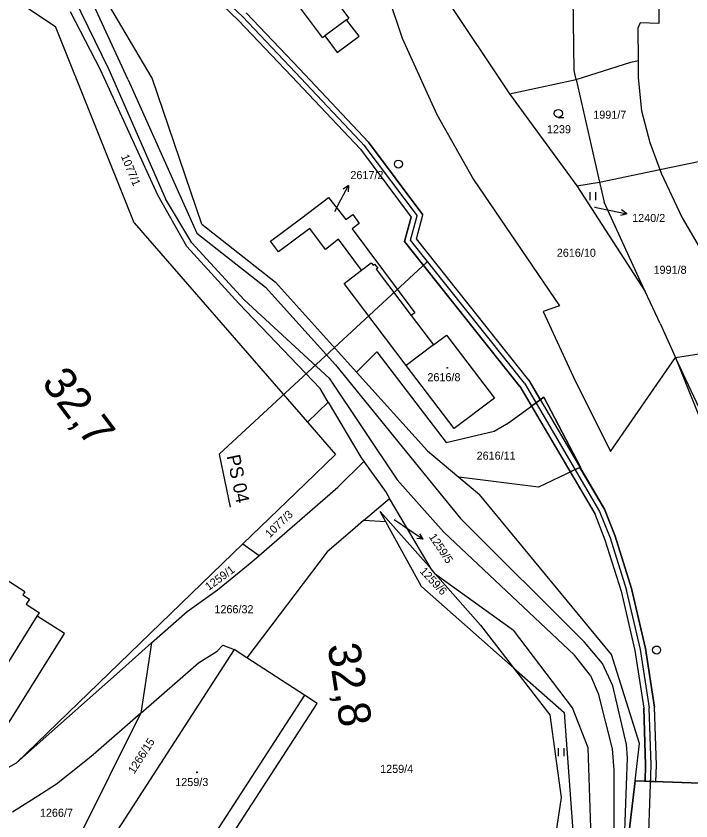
# Model space of a CAD drawing. Extents: x -804166 to -803706, y -1151030 to -1150147.
# Drawn here: x -803978.8 to -803853.6, y -1150580.2 to -1150430.9 of the extents above; entities that cross this region are included whole.
import ezdxf

# ---------------------------------------------------------------- set-up
doc = ezdxf.new("R2010")
doc.units = 0
for name, color, linetype in [('Default', 7, 'Continuous'), ('kilometráž - vrstava 7', 7, 'Continuous'), ('kn_celek - Cisla parcel pomocna', 7, 'Continuous'), ('kn_celek - Cisla pozemkovych parcel', 7, 'Continuous'), ('kn_celek - Cisla stavebnich parcel', 7, 'Continuous'), ('kn_celek - Hranice parcel', 7, 'Continuous'), ('kn_celek - Vnitrni kresby', 7, 'Continuous'), ('kn_celek - Znacky budov', 7, 'Continuous'), ('kn_celek - Znacky kultur', 7, 'Continuous'), ('plochy - CD', 7, 'Continuous'), ('plochy - DZ_ostat', 7, 'Continuous'), ('plochy - SZDC', 7, 'Continuous'), ('plochy - VB', 7, 'Continuous'), ('PSR_C2_2_trasa_Vimperk - Kabelová trasa', 7, 'Continuous'), ('SOPS', 7, 'Continuous')]:
    doc.layers.add(name, color=color, linetype=linetype)

# ---------------------------------------------------------------- blocks, each defined once
blk = doc.blocks.new('304')
at = {"layer": 'Default'}
blk.add_line((-0.1, 0), (9.9, 0), dxfattribs=at)
blk.add_circle((-0.1, 7.5), 7.5, dxfattribs=at)
blk = doc.blocks.new('306')
at = {"layer": 'Default'}
for p, q in [((-5.2, 0), (-5.2, 15)), ((4.8, 0), (4.8, 15))]:
    blk.add_line(p, q, dxfattribs=at)
blk = doc.blocks.new('402')
at = {"layer": 'Default'}
for p, q in [((-0.8, 0.8), (0.7, 0.8)), ((-0.8, 0.8), (-0.8, -0.7)), ((0.7, 0.8), (0.7, -0.7)), ((0.7, -0.7), (-0.8, -0.7))]:
    blk.add_line(p, q, dxfattribs=at)
blk = doc.blocks.new('Z61')
at = {"layer": 'Default'}
for p, q in [((0, 0), (30, 0)), ((30, 0), (19.2, 5.3)), ((30, 0), (19.2, -5.3))]:
    blk.add_line(p, q, dxfattribs=at)

msp = doc.modelspace()

# ---------------------------------------------------------------- linework, layer by layer
at = {"layer": 'kilometráž - vrstava 7'}
for centre in [(-803907.87, -1150458.35), (-803859.96, -1150548.47)]:
    msp.add_circle(centre, 0.75, dxfattribs=at)
at = {"layer": 'kn_celek - Cisla parcel pomocna'}
for p, q in [((-803919.68, -1150467.14), (-803918.53, -1150464.96)), ((-803871.51, -1150466.36), (-803868.44, -1150466.99)), ((-803908.68, -1150524.26), (-803905.75, -1150526.25))]:
    msp.add_line(p, q, dxfattribs=at)
at = {"layer": 'kn_celek - Hranice parcel'}
for p, q in [((-804026.79, -1150395.95), (-803971.47, -1150432.84)), ((-803859.7, -1150404.14), (-803859.55, -1150432.31)), ((-803875.26, -1150441.02), (-803875.68, -1150406.78)), ((-803932.96, -1150410.23), (-803917.09, -1150431.3)), ((-803921.93, -1150434.85), (-803937.77, -1150413.78)), ((-803903.99, -1150420.19), (-803887.28, -1150445.33)), ((-803953.58, -1150442.45), (-803965.92, -1150421.41)), ((-803909.89, -1150426.9), (-803907.15, -1150435.03)), ((-803963.14, -1150440.87), (-803968.72, -1150430.14)), ((-803917.49, -1150431.6), (-803917.09, -1150431.3)), ((-803915.17, -1150434.66), (-803917.49, -1150431.6)), ((-803863.03, -1150432.19), (-803863.45, -1150433.16)), ((-803859.55, -1150432.31), (-803863.03, -1150432.19)), ((-803956.89, -1150469.24), (-803971.47, -1150432.84)), ((-803863.45, -1150433.16), (-803863.4, -1150439.15)), ((-803921.93, -1150434.85), (-803921.53, -1150434.55)), ((-803921.53, -1150434.55), (-803919.22, -1150437.65)), ((-803919.22, -1150437.65), (-803915.17, -1150434.66)), ((-803907.15, -1150435.03), (-803900.76, -1150449.16)), ((-803874.89, -1150442.65), (-803864.75, -1150439.43)), ((-803864.75, -1150439.43), (-803863.4, -1150439.15)), ((-803863.4, -1150439.15), (-803863.37, -1150442.39)), ((-803952.5, -1150464.09), (-803963.14, -1150440.87)), ((-803874.89, -1150442.65), (-803875.26, -1150441.02)), ((-803944.36, -1150469.51), (-803953.58, -1150442.45)), ((-803887.28, -1150445.33), (-803874.89, -1150442.65)), ((-803874.89, -1150442.65), (-803870.54, -1150461.68)), ((-803863.37, -1150442.39), (-803862.79, -1150448.49)), ((-803887.28, -1150445.33), (-803874.77, -1150462.41)), ((-803862.79, -1150448.49), (-803861.22, -1150454.33)), ((-803900.76, -1150449.16), (-803893.94, -1150461.19)), ((-803861.22, -1150454.33), (-803859.37, -1150459.36)), ((-803859.37, -1150459.36), (-803848.47, -1150457.09)), ((-803870.54, -1150461.68), (-803859.37, -1150459.36)), ((-803859.37, -1150459.36), (-803859.13, -1150460.01)), ((-803859.13, -1150460.01), (-803855.19, -1150468.33)), ((-803893.94, -1150461.19), (-803877.95, -1150484.62)), ((-803874.77, -1150462.41), (-803870.54, -1150461.68)), ((-803870.54, -1150461.68), (-803869.68, -1150465.41)), ((-803874.77, -1150462.41), (-803862.07, -1150481.98)), ((-803947.12, -1150473.61), (-803952.5, -1150464.09)), ((-803925.79, -1150468.33), (-803920.83, -1150464.56)), ((-803920.83, -1150464.56), (-803917.63, -1150468.64)), ((-803863.6, -1150478.64), (-803869.68, -1150465.41)), ((-803917.63, -1150468.64), (-803916.3, -1150467.69)), ((-803916.3, -1150467.69), (-803915.12, -1150469.35)), ((-803956.89, -1150469.24), (-803924.74, -1150506.24)), ((-803944.36, -1150469.51), (-803930.65, -1150480.27)), ((-803931.57, -1150472.66), (-803925.79, -1150468.33)), ((-803915.12, -1150469.35), (-803916.46, -1150470.34)), ((-803855.19, -1150468.33), (-803852.25, -1150473.4)), ((-803924.33, -1150470.27), (-803930.11, -1150474.6)), ((-803921.41, -1150474.2), (-803924.33, -1150470.27)), ((-803916.46, -1150470.34), (-803904.84, -1150485.91)), ((-803930.11, -1150474.6), (-803931.57, -1150472.66)), ((-803919.01, -1150472.26), (-803921.41, -1150474.2)), ((-803914.71, -1150478.01), (-803919.01, -1150472.26)), ((-803947.12, -1150473.61), (-803937.45, -1150484.2)), ((-803914.71, -1150478.01), (-803912.92, -1150476.64)), ((-803912.92, -1150476.64), (-803912.56, -1150477.11)), ((-803912.56, -1150477.11), (-803912.3, -1150476.91)), ((-803912.3, -1150476.91), (-803911.71, -1150477.67)), ((-803917.95, -1150480.48), (-803914.71, -1150478.01)), ((-803911.71, -1150477.67), (-803911.98, -1150477.87)), ((-803911.98, -1150477.87), (-803905.5, -1150486.41)), ((-803862.07, -1150481.98), (-803863.6, -1150478.64)), ((-803915.62, -1150496.95), (-803930.65, -1150480.27)), ((-803906.42, -1150495.69), (-803917.95, -1150480.48)), ((-803859.3, -1150487.93), (-803862.07, -1150481.98)), ((-803937.45, -1150484.2), (-803922.41, -1150499.99)), ((-803877.95, -1150484.62), (-803881.02, -1150485.69)), ((-803904.84, -1150485.91), (-803905.5, -1150486.41)), ((-803881.02, -1150485.69), (-803875.42, -1150497.74)), ((-803905.5, -1150486.41), (-803901.34, -1150491.89)), ((-803859.3, -1150487.93), (-803856.47, -1150494.21)), ((-803901.34, -1150491.89), (-803898.96, -1150490.08)), ((-803898.96, -1150490.08), (-803890.06, -1150501.75)), ((-803856.47, -1150494.21), (-803836.01, -1150490.97)), ((-803915.62, -1150496.95), (-803911.88, -1150493.16)), ((-803911.88, -1150493.16), (-803899.02, -1150510.01)), ((-803868.53, -1150511.63), (-803856.47, -1150494.21)), ((-803851.14, -1150505.55), (-803856.47, -1150494.21)), ((-803856.47, -1150494.21), (-803850.2, -1150509.77)), ((-803897.53, -1150507.41), (-803906.42, -1150495.69)), ((-803902.47, -1150511.55), (-803915.62, -1150496.95)), ((-803875.42, -1150497.74), (-803868.53, -1150511.63)), ((-803920.92, -1150502.5), (-803922.41, -1150499.99)), ((-803924.74, -1150506.24), (-803920.92, -1150502.5)), ((-803920.92, -1150502.5), (-803914.87, -1150512.69)), ((-803890.06, -1150501.75), (-803897.53, -1150507.41)), ((-803887.46, -1150506.35), (-803880.9, -1150501.6)), ((-803880.9, -1150501.6), (-803874.06, -1150514.53)), ((-803924.74, -1150506.24), (-803919.56, -1150512.21)), ((-803890.08, -1150507.89), (-803887.46, -1150506.35)), ((-803899.02, -1150510.01), (-803890.08, -1150507.89)), ((-803919.56, -1150512.21), (-803925.19, -1150517.65)), ((-803914.87, -1150512.69), (-803914.28, -1150513.51)), ((-803902.47, -1150511.55), (-803896.64, -1150516.44)), ((-803919.12, -1150518.27), (-803914.28, -1150513.51)), ((-803914.28, -1150513.51), (-803910.12, -1150519.28)), ((-803874.06, -1150514.53), (-803881.88, -1150518.24)), ((-803881.88, -1150518.24), (-803896.64, -1150516.44)), ((-803896.64, -1150516.44), (-803892.84, -1150519.63)), ((-803925.19, -1150517.65), (-803936.74, -1150528.8)), ((-803933.72, -1150530.91), (-803919.12, -1150518.27)), ((-803914.32, -1150524.45), (-803909.5, -1150520.37)), ((-803910.12, -1150519.28), (-803909.5, -1150520.37)), ((-803901.82, -1150533.43), (-803909.5, -1150520.37)), ((-803868.33, -1150549.32), (-803892.84, -1150519.63)), ((-803911.26, -1150522.75), (-803901.82, -1150533.43)), ((-803910.2, -1150524.68), (-803911.26, -1150522.75)), ((-803914.32, -1150524.45), (-803916.41, -1150526.21)), ((-803910.2, -1150524.68), (-803914.32, -1150524.45)), ((-803903.57, -1150536.7), (-803910.2, -1150524.68)), ((-803916.41, -1150526.21), (-803921.06, -1150530.26)), ((-803936.74, -1150528.8), (-803978.76, -1150569.37)), ((-803936.74, -1150528.8), (-803933.72, -1150530.91)), ((-803921.06, -1150530.26), (-803935.98, -1150549.91)), ((-803935.07, -1150532.08), (-803933.72, -1150530.91)), ((-803941.43, -1150537.31), (-803935.07, -1150532.08)), ((-803901.02, -1150534.33), (-803901.82, -1150533.43)), ((-803977.17, -1150537.66), (-803981.93, -1150534.66)), ((-803901.02, -1150534.33), (-803892.62, -1150543.83)), ((-803901.02, -1150534.33), (-803886.49, -1150544.79)), ((-803886.5, -1150551.75), (-803903.57, -1150536.7)), ((-803977.17, -1150537.66), (-803977.55, -1150538.26)), ((-803977.55, -1150538.26), (-803976.32, -1150539.03)), ((-803947.05, -1150541.29), (-803941.43, -1150537.31)), ((-803976.32, -1150539.03), (-803976.94, -1150539.99)), ((-803976.94, -1150539.99), (-803974.49, -1150541.55)), ((-803953.66, -1150547.14), (-803947.05, -1150541.29)), ((-803974.91, -1150542.21), (-803974.49, -1150541.55)), ((-803969.82, -1150545.4), (-803974.91, -1150542.21)), ((-803892.62, -1150543.83), (-803886.5, -1150551.75)), ((-803986.49, -1150572.01), (-803969.82, -1150545.4)), ((-803875.55, -1150559.18), (-803886.49, -1150544.79)), ((-803959.08, -1150551.94), (-803953.66, -1150547.14)), ((-803953.66, -1150547.14), (-803955.66, -1150560.2)), ((-803938.33, -1150548.38), (-803963.12, -1150586.6)), ((-803944.95, -1150550.83), (-803941.49, -1150548.68)), ((-803941.49, -1150548.68), (-803940.44, -1150547.56)), ((-803940.44, -1150547.56), (-803938.33, -1150548.38)), ((-803935.98, -1150549.91), (-803938.33, -1150548.38)), ((-803925.31, -1150556.84), (-803935.98, -1150549.91)), ((-803863.11, -1150565.8), (-803868.33, -1150549.32)), ((-803955.66, -1150560.2), (-803944.95, -1150550.83)), ((-803886.5, -1150551.75), (-803881.66, -1150558.03)), ((-803886.5, -1150551.75), (-803877.12, -1150560.03)), ((-803978.76, -1150569.37), (-803959.08, -1150551.94)), ((-803922.92, -1150558.39), (-803925.31, -1150556.84)), ((-803941.24, -1150586.55), (-803922.92, -1150558.39)), ((-803881.66, -1150558.03), (-803879.76, -1150560.49)), ((-803872.68, -1150566.63), (-803875.55, -1150559.18)), ((-803968.67, -1150586.34), (-803955.66, -1150560.2)), ((-803955.66, -1150560.2), (-803964.49, -1150567.92)), ((-803879.76, -1150560.49), (-803877.66, -1150575.81)), ((-803877.12, -1150560.03), (-803875.07, -1150587.8)), ((-803872.16, -1150581.41), (-803872.68, -1150566.63)), ((-803863.95, -1150572.75), (-803863.11, -1150565.8)), ((-803964.49, -1150567.92), (-803966.17, -1150569.26)), ((-803987.15, -1150574.13), (-803978.76, -1150569.37)), ((-803966.17, -1150569.26), (-803971.31, -1150573.36)), ((-803971.31, -1150573.36), (-803974.11, -1150575.13)), ((-803868.49, -1150610.44), (-803863.95, -1150572.75)), ((-803863.95, -1150572.75), (-803843.4, -1150573.43)), ((-803974.11, -1150575.13), (-803979.5, -1150578.55)), ((-803877.66, -1150575.81), (-803880.42, -1150594.27))]:
    msp.add_line(p, q, dxfattribs=at)
at = {"layer": 'kn_celek - Vnitrni kresby'}
for p, q in [((-803958.04, -1150442.71), (-803967.2, -1150422.72)), ((-803969.03, -1150425.49), (-803961.6, -1150440.81)), ((-803917.49, -1150431.6), (-803921.53, -1150434.55)), ((-803961.6, -1150440.81), (-803951.09, -1150464.8)), ((-803958.04, -1150442.71), (-803945.3, -1150471.15)), ((-803946.22, -1150472.96), (-803951.09, -1150464.8)), ((-803945.3, -1150471.15), (-803932.55, -1150481.19)), ((-803946.22, -1150472.96), (-803936.5, -1150483.51)), ((-803932.55, -1150481.19), (-803919.53, -1150495.55)), ((-803936.5, -1150483.51), (-803920.69, -1150498.06)), ((-803901.34, -1150491.89), (-803906.42, -1150495.69)), ((-803919.53, -1150495.55), (-803901.01, -1150518.41)), ((-803920.69, -1150498.06), (-803908.11, -1150516.88)), ((-803908.11, -1150516.88), (-803899.46, -1150526.63)), ((-803901.01, -1150518.41), (-803896.36, -1150524.1)), ((-803896.36, -1150524.1), (-803873.36, -1150547.03)), ((-803875.18, -1150549.43), (-803899.46, -1150526.63)), ((-803989.99, -1150566.17), (-803974.91, -1150542.21)), ((-803870.02, -1150550.99), (-803873.36, -1150547.03)), ((-803872.23, -1150553.16), (-803875.18, -1150549.43)), ((-803868.09, -1150555.1), (-803870.02, -1150550.99)), ((-803872.23, -1150553.16), (-803870.78, -1150556.51)), ((-803865.52, -1150565.98), (-803868.09, -1150555.1)), ((-803925.31, -1150556.84), (-803943.57, -1150584.97)), ((-803870.78, -1150556.51), (-803868.22, -1150566.79)), ((-803865.36, -1150568.45), (-803865.52, -1150565.98)), ((-803868.22, -1150566.79), (-803867.92, -1150570.66)), ((-803865.9, -1150583.94), (-803865.36, -1150568.45)), ((-803867.92, -1150570.66), (-803867.87, -1150583.73))]:
    msp.add_line(p, q, dxfattribs=at)
at = {"layer": 'plochy - CD'}
for p, q in [((-803945.37, -1150424.23), (-803937.53, -1150431.71)), ((-803926.23, -1150440.67), (-803936.11, -1150430.3)), ((-803937.53, -1150431.71), (-803927.68, -1150442.04)), ((-803913.4, -1150454.32), (-803926.23, -1150440.67)), ((-803927.68, -1150442.04), (-803914.93, -1150455.61)), ((-803903.32, -1150467.76), (-803913.4, -1150454.32)), ((-803914.93, -1150455.61), (-803905.51, -1150468.18)), ((-803881.54, -1150502.07), (-803883.67, -1150498.44)), ((-803883.17, -1150503.24), (-803881.54, -1150502.07)), ((-803874.18, -1150514.59), (-803876, -1150515.45)), ((-803876, -1150515.45), (-803871.43, -1150523.22)), ((-803869.62, -1150522.34), (-803874.18, -1150514.59)), ((-803871.43, -1150523.22), (-803869.54, -1150528.03)), ((-803867.65, -1150527.36), (-803869.62, -1150522.34)), ((-803864.62, -1150537.05), (-803867.65, -1150527.36)), ((-803869.54, -1150528.03), (-803866.56, -1150537.58)), ((-803866.56, -1150537.58), (-803863.99, -1150548.57)), ((-803862.02, -1150548.19), (-803864.62, -1150537.05)), ((-803863.99, -1150548.57), (-803862.33, -1150559.27)), ((-803860.33, -1150559.09), (-803862.02, -1150548.19))]:
    msp.add_line(p, q, dxfattribs=at)
for points in [[(-803905.51, -1150468.18), (-803906.72, -1150472.68), (-803885.37, -1150499.52)], [(-803883.67, -1150498.44), (-803904.53, -1150472.23), (-803903.32, -1150467.76)], [(-803885.37, -1150499.52), (-803885.36, -1150499.51)], [(-803885.36, -1150499.51), (-803885.33, -1150499.57), (-803883.17, -1150503.24)], [(-803862.33, -1150559.27), (-803862, -1150569.82), (-803862.1, -1150572.81)], [(-803862.1, -1150572.81), (-803860.1, -1150572.88), (-803860, -1150569.82), (-803860.33, -1150559.09)]]:
    msp.add_lwpolyline(points, dxfattribs=at)
at = {"layer": 'plochy - DZ_ostat'}
for p, q in [((-803885.36, -1150499.51), (-803871.39, -1150523.29)), ((-803880.9, -1150501.6), (-803883.17, -1150503.24)), ((-803874.06, -1150514.53), (-803880.9, -1150501.6)), ((-803883.17, -1150503.24), (-803876, -1150515.45)), ((-803876, -1150515.45), (-803874.06, -1150514.53))]:
    msp.add_line(p, q, dxfattribs=at)
at = {"layer": 'plochy - SZDC'}
for p, q in [((-803863.95, -1150572.75), (-803868.49, -1150610.44)), ((-803843.4, -1150573.43), (-803863.95, -1150572.75))]:
    msp.add_line(p, q, dxfattribs=at)
at = {"layer": 'plochy - VB'}
for p, q in [((-803945.37, -1150424.23), (-803937.53, -1150431.71)), ((-803936.11, -1150430.3), (-803926.23, -1150440.67)), ((-803937.53, -1150431.71), (-803927.68, -1150442.04)), ((-803926.23, -1150440.67), (-803913.4, -1150454.32)), ((-803927.68, -1150442.04), (-803914.93, -1150455.61)), ((-803913.4, -1150454.32), (-803903.32, -1150467.76)), ((-803914.93, -1150455.61), (-803905.51, -1150468.18)), ((-803885.33, -1150499.57), (-803871.43, -1150523.22)), ((-803883.67, -1150498.44), (-803869.62, -1150522.34)), ((-803871.43, -1150523.22), (-803869.54, -1150528.03)), ((-803869.62, -1150522.34), (-803867.65, -1150527.36)), ((-803867.65, -1150527.36), (-803864.62, -1150537.05)), ((-803869.54, -1150528.03), (-803866.56, -1150537.58)), ((-803866.56, -1150537.58), (-803863.99, -1150548.57)), ((-803864.62, -1150537.05), (-803862.02, -1150548.19)), ((-803863.99, -1150548.57), (-803862.33, -1150559.27)), ((-803862.02, -1150548.19), (-803860.33, -1150559.09))]:
    msp.add_line(p, q, dxfattribs=at)
for points in [[(-803885.33, -1150499.57), (-803906.72, -1150472.68), (-803905.51, -1150468.18)], [(-803883.67, -1150498.44), (-803904.53, -1150472.23), (-803903.32, -1150467.76)], [(-803862.1, -1150572.81), (-803862, -1150569.82), (-803862.33, -1150559.27)], [(-803862.1, -1150572.81), (-803860.1, -1150572.88), (-803860, -1150569.82), (-803860.33, -1150559.09)]]:
    msp.add_lwpolyline(points, dxfattribs=at)
at = {"layer": 'PSR_C2_2_trasa_Vimperk - Kabelová trasa'}
for p, q in [((-803944.68, -1150423.51), (-803936.82, -1150431)), ((-803936.82, -1150431), (-803926.95, -1150441.36)), ((-803926.95, -1150441.36), (-803914.05, -1150455.09)), ((-803914.26, -1150454.83), (-803904.41, -1150467.97)), ((-803884.5, -1150499), (-803870.53, -1150522.78)), ((-803870.53, -1150522.78), (-803868.59, -1150527.69)), ((-803868.59, -1150527.69), (-803865.57, -1150537.39)), ((-803865.59, -1150537.32), (-803863, -1150548.38)), ((-803863, -1150548.38), (-803861.33, -1150559.18))]:
    msp.add_line(p, q, dxfattribs=at)
for points in [[(-803884.5, -1150499), (-803905.62, -1150472.45), (-803904.41, -1150467.97)], [(-803868.21, -1150616.46), (-803863.02, -1150600.18), (-803861.64, -1150589.37), (-803861, -1150569.82), (-803861.33, -1150559.18)]]:
    msp.add_lwpolyline(points, dxfattribs=at)
at = {"layer": 'SOPS'}
for p, q in [((-803902.58, -1150476.55), (-803941.11, -1150512.13)), ((-803941.11, -1150512.13), (-803939.07, -1150521.98))]:
    msp.add_line(p, q, dxfattribs=at)

# ---------------------------------------------------------------- block references
at = {"layer": 'kn_celek - Cisla parcel pomocna'}
for p, xscale, yscale, rotation in [((-803918.53, -1150464.96), 0.1, 0.10000000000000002, 62.11665000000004), ((-803868.44, -1150466.99), 0.1, 0.10000000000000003, -11.657699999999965), ((-803905.75, -1150526.25), 0.09999999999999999, 0.1, -34.22447999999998)]:
    msp.add_blockref('Z61', p, dxfattribs=dict(at, xscale=xscale, yscale=yscale, rotation=rotation))
at = {"layer": 'kn_celek - Znacky budov', "xscale": 0.1, "yscale": 0.10000000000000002}
for p in [(-803898.83, -1150496.13), (-803945.28, -1150571.14)]:
    msp.add_blockref('402', p, dxfattribs=at)
at = {"layer": 'kn_celek - Znacky kultur', "xscale": 0.1, "yscale": 0.10000000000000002}
for name, p in [('304', (-803878.19, -1150449.71)), ('306', (-803871.74, -1150465.05)), ('306', (-803877.62, -1150568.15))]:
    msp.add_blockref(name, p, dxfattribs=at)

# ---------------------------------------------------------------- texts
at = {"layer": 'kilometráž - vrstava 7'}
for s, rotation, p in [('32,7', 306.901, (-803974.22, -1150498.93)), ('32,8', 278.8223, (-803921.04, -1150547.59))]:
    msp.add_text(s, height=6, rotation=rotation, dxfattribs=at).set_placement(p)
at = {"layer": 'kn_celek - Cisla parcel pomocna'}
for s, p in [('2617/2', (-803916.78, -1150461.14)), ('1240/2', (-803864.5, -1150469.1))]:
    msp.add_text(s, height=1.5, dxfattribs=at).set_placement(p)
msp.add_text('1259/5', height=1.5, rotation=303.6901, dxfattribs=at).set_placement((-803902.27, -1150527.47))
at = {"layer": 'kn_celek - Cisla pozemkovych parcel'}
for s, height, p in [('1991/7', 1.5, (-803871.71, -1150449.94)), ('1239', 1.5, (-803880.31, -1150452.64)), ('1240/2', 0.1, (-803871.51, -1150466.33)), ('2617/2', 0.1, (-803919.68, -1150467.11)), ('2616/10', 1.5, (-803878.48, -1150475.55)), ('1991/8', 1.5, (-803860.53, -1150478.7)), ('2616/11', 1.5, (-803893.36, -1150513.17)), ('1259/5', 0.1, (-803908.68, -1150524.23)), ('1266/32', 1.5, (-803942.01, -1150541.65)), ('1259/4', 1.5, (-803911.26, -1150571.25)), ('1266/7', 1.5, (-803974.39, -1150579.39))]:
    msp.add_text(s, height=height, dxfattribs=at).set_placement(p)
for s, rotation, p in [('1077/1', 292.5, (-803959.38, -1150456.9)), ('1077/3', 43.8883, (-803931.73, -1150527.74)), ('1259/1', 36, (-803943.06, -1150537.5)), ('1259/6', 313.2, (-803904, -1150533.95)), ('1266/15', 57.6, (-803956.89, -1150571.55))]:
    msp.add_text(s, height=1.5, rotation=rotation, dxfattribs=at).set_placement(p)
at = {"layer": 'kn_celek - Cisla stavebnich parcel'}
for s, p in [('2616/8', (-803902.49, -1150498.62)), ('1259/3', (-803949.27, -1150573.69))]:
    msp.add_text(s, height=1.5, dxfattribs=at).set_placement(p)
at = {"layer": 'SOPS'}
msp.add_text('PS 04', height=2.5, rotation=281.6652, dxfattribs=at).set_placement((-803939.75, -1150512.49))

doc.saveas('drawing.dxf')
